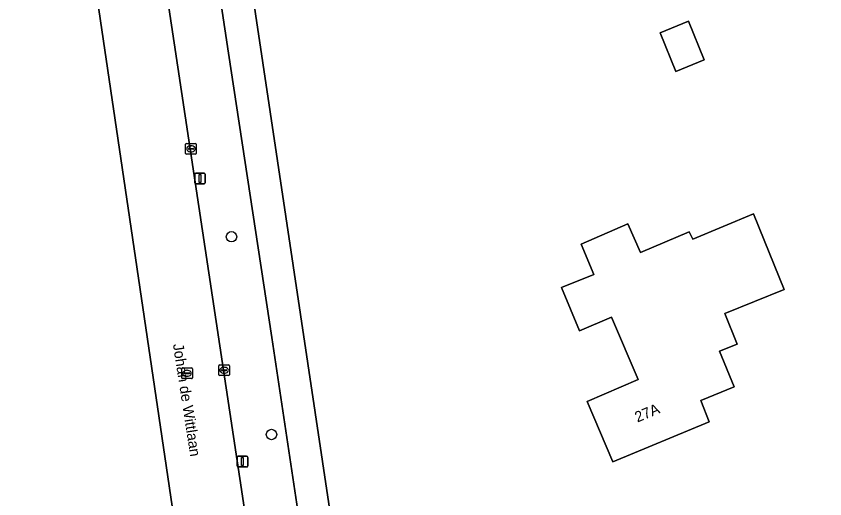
# Model space of a CAD drawing. Extents: x 162417 to 163722, y 384268 to 385417.
# Drawn here: x 163157.7 to 163233.6, y 384821.1 to 384866.4 of the extents above; entities that cross this region are included whole.
import ezdxf

# ---------------------------------------------------------------- set-up
doc = ezdxf.new("R2010")
doc.units = 0
for name, color, linetype in [('IMGEO_Berm_groen', 7, 'Continuous'), ('IMGEO_Boom', 7, 'Continuous'), ('IMGEO_Erf', 7, 'Continuous'), ('IMGEO_Kolk', 7, 'Continuous'), ('IMGEO_Lichtmast', 7, 'Continuous'), ('IMGEO_Openbare_ruimte_label', 7, 'Continuous'), ('IMGEO_Pand', 7, 'Continuous'), ('IMGEO_Pand_nummerreeks', 7, 'Continuous'), ('IMGEO_Rijbaan_lokaal_gesloten', 7, 'Continuous'), ('IMGEO_Rioolput', 7, 'Continuous'), ('IMGEO_Voetpad_open', 7, 'Continuous')]:
    doc.layers.add(name, color=color, linetype=linetype)

msp = doc.modelspace()

# ---------------------------------------------------------------- linework, layer by layer
at = {"layer": 'IMGEO_Berm_groen'}
for points in [[(163177.654, 384862.939), (163176.986, 384867.512), (163176.027, 384874.074), (163175.599, 384877.142), (163174.611, 384883.435), (163173.131, 384893.686), (163168.375, 384891.762), (163181.052, 384807.665)], [(163186.458, 384804.456), (163185.853, 384808.72), (163181.731, 384836.256), (163177.654, 384862.939)]]:
    msp.add_lwpolyline(points, dxfattribs=at)
at = {"layer": 'IMGEO_Boom'}
for centre in [(163177.939, 384845.707), (163181.699, 384827.146)]:
    msp.add_circle(centre, 0.489, dxfattribs=at)
at = {"layer": 'IMGEO_Erf'}
msp.add_lwpolyline([(163355.108, 384922.849), (163338.205, 384963.202), (163332.037, 384960.636), (163331.845, 384960.556), (163328.115, 384959.004), (163309.804, 384951.385), (163305.952, 384950.098), (163301.519, 384948.918), (163287.113, 384942.953), (163279.759, 384939.573), (163273.176, 384936.418), (163263.164, 384931.62), (163230.9, 384918.02), (163227.943, 384916.773), (163202.03, 384905.85), (163198.14, 384904.21), (163175.984, 384894.871), (163189.317, 384805.604)], dxfattribs=at)
for points in [[(163159.564, 384907.094), (163168.293, 384913.998), (163151.904, 384951.836), (163097.149, 384943.131), (163103.623, 384899.24), (163109.03, 384862.7), (163116.803, 384810.173), (163172.668, 384818.516)], [(163218.184, 384864.853), (163220.841, 384865.931), (163222.313, 384862.302), (163219.657, 384861.224)], [(163227.923, 384845.387), (163229.802, 384840.753), (163224.242, 384838.497), (163225.407, 384835.624), (163223.757, 384834.954), (163225.11, 384831.618), (163221.98, 384830.348), (163222.787, 384828.346), (163213.737, 384824.576), (163211.31, 384830.26), (163216.121, 384832.314), (163213.618, 384838.15), (163210.603, 384836.863), (163208.906, 384840.934), (163211.965, 384842.153), (163210.776, 384844.998), (163215.14, 384846.909), (163216.318, 384844.229), (163220.899, 384846.157), (163221.245, 384845.478), (163226.923, 384847.852)]]:
    msp.add_lwpolyline(points, close=True, dxfattribs=at)
at = {"layer": 'IMGEO_Kolk'}
for p, q in [((163173.636, 384853.535), (163173.636, 384854.387)), ((163173.711, 384854.461), (163174.563, 384854.461)), ((163173.895, 384853.955), (163173.895, 384853.967)), ((163174.333, 384853.918), (163173.935, 384853.918)), ((163173.938, 384854.004), (163174.336, 384854.004)), ((163174.124, 384854.241), (163174.149, 384854.241)), ((163174.379, 384853.967), (163174.379, 384853.955)), ((163174.637, 384854.387), (163174.637, 384853.535)), ((163174.563, 384853.461), (163173.711, 384853.461)), ((163174.147, 384853.681), (163174.122, 384853.681)), ((163176.744, 384832.756), (163176.744, 384833.608)), ((163176.819, 384833.682), (163177.671, 384833.682)), ((163177.232, 384833.462), (163177.257, 384833.462)), ((163177.745, 384833.608), (163177.745, 384832.756)), ((163177.671, 384832.682), (163176.819, 384832.682)), ((163177.003, 384833.176), (163177.003, 384833.188)), ((163177.441, 384833.139), (163177.043, 384833.139)), ((163177.046, 384833.225), (163177.444, 384833.225)), ((163177.255, 384832.902), (163177.23, 384832.902)), ((163177.487, 384833.188), (163177.487, 384833.176))]:
    msp.add_line(p, q, dxfattribs=at)
for points in [[(163173.636, 384853.535), (163173.636, 384854.387)], [(163173.711, 384854.461), (163174.563, 384854.461)], [(163174.637, 384854.387), (163174.637, 384853.535)], [(163174.563, 384853.461), (163173.711, 384853.461)], [(163176.744, 384832.756), (163176.744, 384833.608)], [(163176.819, 384833.682), (163177.671, 384833.682)], [(163177.745, 384833.608), (163177.745, 384832.756)], [(163177.671, 384832.682), (163176.819, 384832.682)]]:
    msp.add_lwpolyline(points, dxfattribs=at)
for centre, radius, start, end in [((163173.713, 384854.385), 0.0765, 91.55205, 178.44795), ((163173.713, 384854.385), 0.0765, 91.55205, 178.44795), ((163173.935, 384853.964), 0.0403, 85.87752, 175.75265), ((163173.932, 384853.954), 0.0366, 178.93798, 274.71019), ((163174.336, 384853.961), 0.043, 264.86636, 352.45326), ((163174.34, 384853.966), 0.0386, 1.73085, 96.63898), ((163174.561, 384854.385), 0.0765, 1.55205, 88.44795), ((163174.561, 384854.385), 0.0765, 1.55205, 88.44795), ((163173.713, 384853.537), 0.0765, 181.55205, 268.44795), ((163173.713, 384853.537), 0.0765, 181.55205, 268.44795), ((163174.561, 384853.537), 0.0765, 271.55205, 358.44795), ((163174.561, 384853.537), 0.0765, 271.55205, 358.44795), ((163176.821, 384833.606), 0.0765, 91.55205, 178.44795), ((163176.821, 384833.606), 0.0765, 91.55205, 178.44795), ((163177.669, 384833.606), 0.0765, 1.55205, 88.44795), ((163177.669, 384833.606), 0.0765, 1.55205, 88.44795), ((163176.821, 384832.758), 0.0765, 181.55205, 268.44795), ((163176.821, 384832.758), 0.0765, 181.55205, 268.44795), ((163177.043, 384833.185), 0.0403, 85.87752, 175.75265), ((163177.04, 384833.175), 0.0366, 178.93798, 274.71019), ((163177.444, 384833.182), 0.043, 264.86636, 352.45326), ((163177.448, 384833.187), 0.0386, 1.73085, 96.63898), ((163177.669, 384832.758), 0.0765, 271.55205, 358.44795), ((163177.669, 384832.758), 0.0765, 271.55205, 358.44795)]:
    msp.add_arc(centre, radius, start, end, dxfattribs=at)
for centre, major_axis, ratio, start_param, end_param in [((163174.123, 384853.961), (-0.387, 0.002), 0.722429, 4.712389, 7.853982), ((163174.148, 384853.961), (-0.39, 0.002), 0.717154, 1.570796, 4.712389), ((163177.231, 384833.182), (-0.387, 0.002), 0.722429, 4.712389, 7.853982), ((163177.256, 384833.182), (-0.39, 0.002), 0.717154, 1.570796, 4.712389)]:
    msp.add_ellipse(centre, major_axis=major_axis, ratio=ratio, start_param=start_param, end_param=end_param, dxfattribs=at)
at = {"layer": 'IMGEO_Lichtmast'}
for p, q in [((163174.586, 384851.681), (163175.376, 384851.681)), ((163175.376, 384851.681), (163174.586, 384851.681)), ((163174.486, 384850.781), (163174.486, 384851.581)), ((163174.486, 384851.581), (163174.486, 384850.781)), ((163175.476, 384851.581), (163175.476, 384850.781)), ((163175.476, 384850.781), (163175.476, 384851.581)), ((163175.376, 384850.681), (163174.586, 384850.681)), ((163174.586, 384850.681), (163175.376, 384850.681)), ((163178.573, 384825.1), (163179.363, 384825.1)), ((163179.363, 384825.1), (163178.573, 384825.1)), ((163178.473, 384824.2), (163178.473, 384825)), ((163178.473, 384825), (163178.473, 384824.2)), ((163179.463, 384825), (163179.463, 384824.2)), ((163179.463, 384824.2), (163179.463, 384825)), ((163179.363, 384824.1), (163178.573, 384824.1)), ((163178.573, 384824.1), (163179.363, 384824.1))]:
    msp.add_line(p, q, dxfattribs=at)
for points in [[(163174.906, 384851.556), (163175.056, 384851.556), (163175.056, 384850.806), (163174.906, 384850.806), (163174.906, 384851.556)], [(163178.893, 384824.975), (163179.043, 384824.975), (163179.043, 384824.225), (163178.893, 384824.225), (163178.893, 384824.975)]]:
    msp.add_lwpolyline(points, dxfattribs=at)
for centre, start, end in [((163174.586, 384851.581), 90, 180), ((163174.586, 384851.581), 90, 180), ((163175.376, 384851.581), 0, 90), ((163175.376, 384851.581), 360, 90), ((163174.586, 384850.781), 180, 270), ((163174.586, 384850.781), 180, 270), ((163175.376, 384850.781), 270, 0), ((163175.376, 384850.781), 270, 0), ((163178.573, 384825), 90, 180), ((163178.573, 384825), 90, 180), ((163179.363, 384825), 0, 90), ((163179.363, 384825), 360, 90), ((163178.573, 384824.2), 180, 270), ((163178.573, 384824.2), 180, 270), ((163179.363, 384824.2), 270, 0), ((163179.363, 384824.2), 270, 0)]:
    msp.add_arc(centre, 0.1, start, end, dxfattribs=at)
at = {"layer": 'IMGEO_Pand'}
for points in [[(163218.184, 384864.853), (163219.657, 384861.224), (163222.313, 384862.302), (163220.841, 384865.931)], [(163227.923, 384845.387), (163226.923, 384847.852), (163221.245, 384845.478), (163220.899, 384846.157), (163216.318, 384844.229), (163215.14, 384846.909), (163210.776, 384844.998), (163211.965, 384842.153), (163208.906, 384840.934), (163210.603, 384836.863), (163213.618, 384838.15), (163216.121, 384832.314), (163211.31, 384830.26), (163213.737, 384824.576), (163222.787, 384828.346), (163221.98, 384830.348), (163225.11, 384831.618), (163223.757, 384834.954), (163225.407, 384835.624), (163224.242, 384838.497), (163229.802, 384840.753)]]:
    msp.add_lwpolyline(points, close=True, dxfattribs=at)
at = {"layer": 'IMGEO_Rijbaan_lokaal_gesloten'}
for points in [[(163186.272, 384907.759), (163183.667, 384913.961), (163175.758, 384919.851), (163175.467, 384919.624), (163173.108, 384917.782), (163170.764, 384915.952), (163168.293, 384913.998), (163159.564, 384907.094), (163172.668, 384818.516)], [(163181.052, 384807.665), (163168.375, 384891.762), (163167.974, 384894.412), (163167.833, 384895.326)]]:
    msp.add_lwpolyline(points, dxfattribs=at)
at = {"layer": 'IMGEO_Rioolput'}
for p, q in [((163173.344, 384833.394), (163174.196, 384833.394)), ((163173.269, 384832.468), (163173.269, 384833.32)), ((163173.528, 384832.888), (163173.528, 384832.9)), ((163173.966, 384832.851), (163173.568, 384832.851)), ((163173.571, 384832.937), (163173.969, 384832.937)), ((163173.78, 384832.614), (163173.755, 384832.614)), ((163173.757, 384833.174), (163173.782, 384833.174)), ((163174.012, 384832.9), (163174.012, 384832.888)), ((163174.27, 384833.32), (163174.27, 384832.468)), ((163174.196, 384832.394), (163173.344, 384832.394))]:
    msp.add_line(p, q, dxfattribs=at)
for points in [[(163173.344, 384833.394), (163174.196, 384833.394)], [(163173.269, 384832.468), (163173.269, 384833.32)], [(163174.27, 384833.32), (163174.27, 384832.468)], [(163174.196, 384832.394), (163173.344, 384832.394)]]:
    msp.add_lwpolyline(points, dxfattribs=at)
for centre, radius, start, end in [((163173.346, 384833.318), 0.0765, 91.55205, 178.44795), ((163173.346, 384833.318), 0.0765, 91.55205, 178.44795), ((163174.194, 384833.318), 0.0765, 1.55205, 88.44795), ((163174.194, 384833.318), 0.0765, 1.55205, 88.44795), ((163173.568, 384832.897), 0.0403, 85.87752, 175.75265), ((163173.565, 384832.887), 0.0366, 178.93798, 274.71019), ((163173.969, 384832.894), 0.043, 264.86636, 352.45326), ((163173.973, 384832.899), 0.0386, 1.73085, 96.63898), ((163173.346, 384832.47), 0.0765, 181.55205, 268.44795), ((163173.346, 384832.47), 0.0765, 181.55205, 268.44795), ((163174.194, 384832.47), 0.0765, 271.55205, 358.44795), ((163174.194, 384832.47), 0.0765, 271.55205, 358.44795)]:
    msp.add_arc(centre, radius, start, end, dxfattribs=at)
for centre, major_axis, ratio, start_param, end_param in [((163173.756, 384832.894), (-0.387, 0.002), 0.722429, 4.712389, 7.853982), ((163173.781, 384832.894), (-0.39, 0.002), 0.717154, 1.570796, 4.712389)]:
    msp.add_ellipse(centre, major_axis=major_axis, ratio=ratio, start_param=start_param, end_param=end_param, dxfattribs=at)
at = {"layer": 'IMGEO_Voetpad_open'}
msp.add_lwpolyline([(163175.984, 384894.871), (163173.131, 384893.686), (163174.611, 384883.435), (163175.599, 384877.142), (163176.027, 384874.074), (163176.986, 384867.512), (163177.654, 384862.939), (163181.731, 384836.256), (163185.853, 384808.72), (163186.458, 384804.456), (163186.712, 384804.512), (163189.317, 384805.604)], close=True, dxfattribs=at)

# ---------------------------------------------------------------- texts
at = {"layer": 'IMGEO_Openbare_ruimte_label'}
msp.add_text('Johan de Wittlaan', height=1, rotation=278.8028, dxfattribs=at).set_placement((163172.441, 384835.607))
at = {"layer": 'IMGEO_Pand_nummerreeks'}
msp.add_text('27A', height=1, rotation=22.61537, dxfattribs=at).set_placement((163216.042, 384828.266))

doc.saveas('drawing.dxf')
